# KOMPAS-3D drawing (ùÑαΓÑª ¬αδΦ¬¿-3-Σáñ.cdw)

Referenced files in E:\Моя музыка\VVV\Мои документы\О.О.К.М\: Чертеж крышки.cdw
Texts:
  Крышка
  125 1 126 1 127 1 128 0 50 1|SPDS|125 1 126 1 127 1 128 0 50 1
  129 1 130 1 131 1 132 0 50 1|SPDS|129 1 130 1 131 1 132 0 50 1
  1. Литейные уклоны- 3 , литейные радиусы- 3...5мм.
  Symbol type B
  2. Неуказанные предельные откланения размеров: h14, H14,  IT14 2 .
  Ra 3,2
  Ra 6,3
  Крышка-
  Сталь 45 ГОСТ 1050-88
  ТФ ДГТУ
Dimensions and other numbers on the sheet: 0,75; 1; 3; 80; 6; 4; 10; 8; 2; 100; 32; 130; 0.020; 0,060; 114; 6 отв.; 1:1; 0,82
